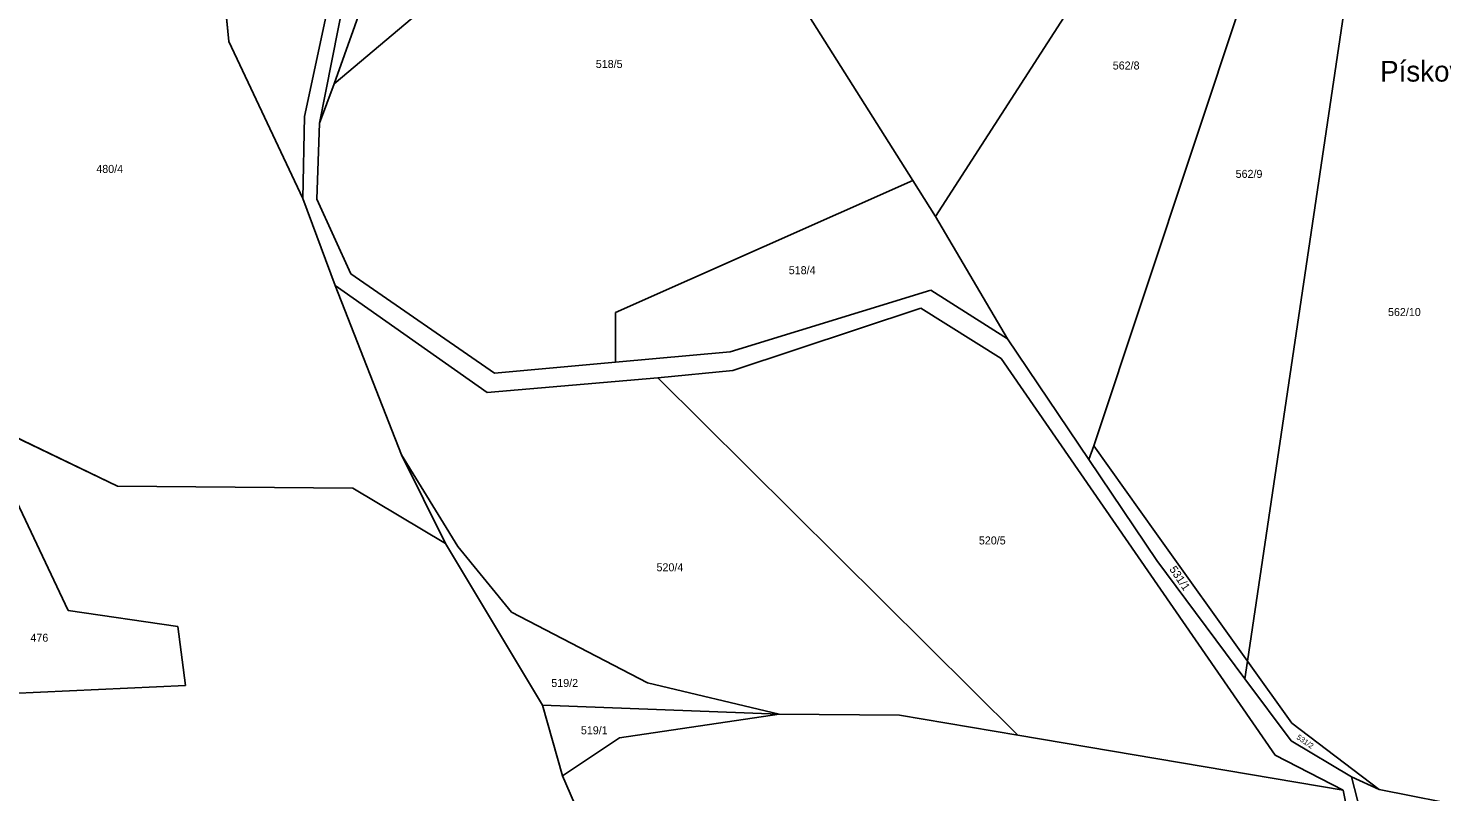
# Model space of a CAD drawing. Extents: x -593358 to -590116, y -1072518 to -1068420.
# Drawn here: x -591348.6 to -591048.4, y -1072084.5 to -1071922.2 of the extents above; entities that cross this region are included whole.
import ezdxf

# ---------------------------------------------------------------- set-up
doc = ezdxf.new("R2010")
doc.units = 0
for name, color, linetype in [('lesy', 7, 'Continuous'), ('Názvosloví', 7, 'Continuous'), ('Parcela KN', 7, 'Continuous'), ('Parcela ZE', 7, 'Continuous'), ('Parcelní číslo', 7, 'Continuous')]:
    doc.layers.add(name, color=color, linetype=linetype)

msp = doc.modelspace()

# ---------------------------------------------------------------- linework, layer by layer
at = {"layer": 'lesy'}
for points in [[(-591308.14, -1071903.51), (-591306.06, -1071924.99), (-591290.33, -1071958.38)], [(-591382.44, -1071994.17), (-591362.03, -1072003.96), (-591345.85, -1072011.725), (-591329.67, -1072019.49), (-591304.69, -1072019.73), (-591279.71, -1072019.97), (-591260.02, -1072031.71)]]:
    msp.add_lwpolyline(points, dxfattribs=at)
at = {"layer": 'Parcela KN'}
for p, q in [((-591083.3, -1071849.49), (-591155.95, -1071962.17)), ((-591241.86, -1071898.7), (-591283.69, -1071934)), ((-591308.14, -1071903.51), (-591306.06, -1071924.99)), ((-591160.75, -1071954.57), (-591189.19, -1071909.47)), ((-591289.98, -1071940.95), (-591283.51, -1071910.71)), ((-591286.79, -1071942.39), (-591280.93, -1071912.65)), ((-591306.06, -1071924.99), (-591290.33, -1071958.38)), ((-591283.69, -1071934), (-591286.79, -1071942.39)), ((-591290.33, -1071958.38), (-591289.98, -1071940.95)), ((-591287.35, -1071958.48), (-591286.79, -1071942.39)), ((-591160.75, -1071954.57), (-591223.91, -1071982.61)), ((-591155.95, -1071962.17), (-591160.75, -1071954.57)), ((-591290.33, -1071958.38), (-591283.45, -1071976.87)), ((-591280.13, -1071974.41), (-591287.35, -1071958.48)), ((-591140.62, -1071988.21), (-591155.95, -1071962.17)), ((-591249.61, -1071995.53), (-591280.13, -1071974.41)), ((-591283.45, -1071976.87), (-591269.36, -1072012.85)), ((-591283.45, -1071976.87), (-591251.19, -1071999.6)), ((-591199.55, -1071990.94), (-591156.92, -1071977.83)), ((-591156.92, -1071977.83), (-591140.62, -1071988.21)), ((-591198.96, -1071994.93), (-591159.05, -1071981.69)), ((-591159.05, -1071981.69), (-591142.01, -1071992.36)), ((-591223.91, -1071982.61), (-591223.89, -1071993.17)), ((-591123.34, -1072013.87), (-591140.62, -1071988.21)), ((-591223.89, -1071993.17), (-591199.55, -1071990.94)), ((-591249.61, -1071995.53), (-591223.89, -1071993.17)), ((-591142.01, -1071992.36), (-591083.82, -1072076.69)), ((-591251.19, -1071999.6), (-591214.88, -1071996.5)), ((-591214.88, -1071996.5), (-591198.96, -1071994.93)), ((-591329.67, -1072019.49), (-591362.03, -1072003.96)), ((-591122.27, -1072010.92), (-591123.34, -1072013.87)), ((-591122.27, -1072010.92), (-591108.97, -1072029.65)), ((-591355.38, -1072013.74), (-591340.12, -1072045.94)), ((-591269.36, -1072012.85), (-591260.02, -1072031.71)), ((-591257.4, -1072032.37), (-591269.36, -1072012.85)), ((-591108.89, -1072035.34), (-591123.34, -1072013.87)), ((-591279.71, -1072019.97), (-591329.67, -1072019.49)), ((-591260.02, -1072031.71), (-591279.71, -1072019.97)), ((-591108.97, -1072029.65), (-591089.65, -1072056.69)), ((-591260.02, -1072031.71), (-591239.37, -1072066.1)), ((-591246, -1072046.31), (-591257.4, -1072032.37)), ((-591090.21, -1072060.47), (-591108.89, -1072035.34)), ((-591340.12, -1072045.94), (-591316.86, -1072049.35)), ((-591217.11, -1072061.36), (-591246, -1072046.31)), ((-591316.86, -1072049.35), (-591315.26, -1072061.91)), ((-591089.65, -1072056.69), (-591080.23, -1072069.88)), ((-591080.42, -1072073.64), (-591090.21, -1072060.47)), ((-591315.26, -1072061.91), (-591352.22, -1072063.59)), ((-591189.17, -1072067.98), (-591217.11, -1072061.36)), ((-591189.17, -1072067.98), (-591239.37, -1072066.1)), ((-591239.37, -1072066.1), (-591235.14, -1072081.07)), ((-591223.02, -1072073.01), (-591189.17, -1072067.98)), ((-591080.23, -1072069.88), (-591061.69, -1072084.01)), ((-591235.14, -1072081.07), (-591223.02, -1072073.01)), ((-591067.61, -1072081.3), (-591080.42, -1072073.64)), ((-591083.82, -1072076.69), (-591069.33, -1072084.12)), ((-591211.56, -1072135.8), (-591235.14, -1072081.07)), ((-591061.69, -1072084.01), (-591067.61, -1072081.3)), ((-591067.61, -1072081.3), (-591064.93, -1072091.69)), ((-591069.33, -1072084.12), (-591067.71, -1072092.3)), ((-591037.49, -1072088.85), (-591061.69, -1072084.01))]:
    msp.add_line(p, q, dxfattribs=at)
at = {"layer": 'Parcela ZE'}
for p, q in [((-591122.27, -1072010.92), (-591073.81, -1071865.02)), ((-591063.7, -1071881.58), (-591089.65, -1072056.69)), ((-591283.69, -1071934), (-591276.55, -1071914)), ((-591214.88, -1071996.5), (-591138.44, -1072072.47)), ((-591089.65, -1072056.69), (-591090.21, -1072060.47)), ((-591189.17, -1072067.98), (-591163.6, -1072068.23)), ((-591163.6, -1072068.23), (-591138.44, -1072072.47)), ((-591138.44, -1072072.47), (-591069.33, -1072084.12))]:
    msp.add_line(p, q, dxfattribs=at)

# ---------------------------------------------------------------- texts
at = {"layer": 'Názvosloví'}
msp.add_text('Pískovna', height=4.4, dxfattribs=at).set_placement((-591061.486, -1071933.52))
at = {"layer": 'Parcelní číslo'}
for s, p in [('518/5', (-591228.086, -1071930.62)), ('562/8', (-591118.284, -1071930.95)), ('480/4', (-591334.177, -1071952.93)), ('562/9', (-591092.184, -1071953.99)), ('518/4', (-591187.099, -1071974.46)), ('562/10', (-591059.822, -1071983.36)), ('520/5', (-591146.717, -1072031.91)), ('520/4', (-591215.19, -1072037.62)), ('476', (-591348.164, -1072052.59)), ('519/2', (-591237.536, -1072062.21)), ('519/1', (-591231.254, -1072072.27))]:
    msp.add_text(s, height=1.7, dxfattribs=at).set_placement(p)
for s, height, rotation, p in [('531/1', 1.7, 303.83952, (-591106.329, -1072037.185)), ('531/2', 1.14, 325.55462, (-591079.361, -1072073.161))]:
    msp.add_text(s, height=height, rotation=rotation, dxfattribs=at).set_placement(p)

doc.saveas('drawing.dxf')
